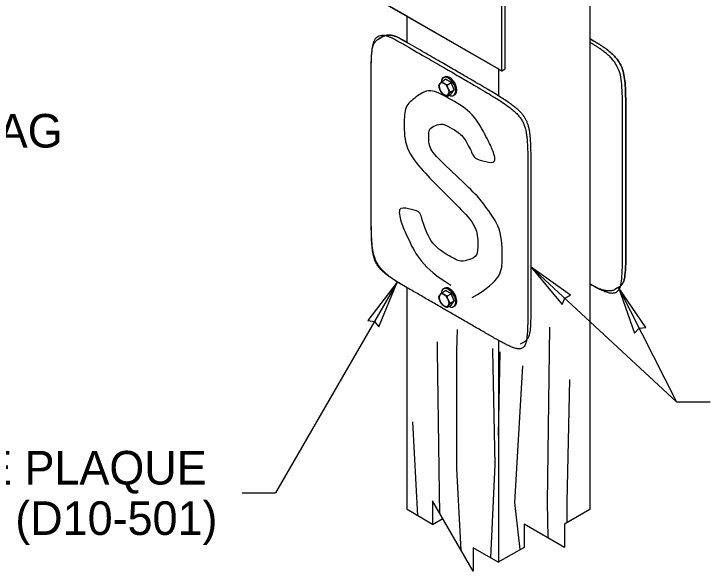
# Model space of a CAD drawing. Extents: x 99862 to 103151, y 100000 to 102076.
# Drawn here: x 101949.6 to 102281.3, y 100780.9 to 101046.3 of the extents above; entities that cross this region are included whole.
import ezdxf

# ---------------------------------------------------------------- set-up
doc = ezdxf.new("R2010")
doc.units = 0
for name, color, linetype in [('Level 11', 7, 'Continuous'), ('Level 15', 7, 'Continuous'), ('Level 2', 7, 'Continuous'), ('Level 20', 7, 'Continuous'), ('Level 9', 7, 'Continuous')]:
    doc.layers.add(name, color=color, linetype=linetype)

msp = doc.modelspace()

# ---------------------------------------------------------------- linework, layer by layer
at = {"layer": 'Level 11'}
for points in [[(102160.68, 100886.06), (102160.91, 100895.92)], [(102203.82, 100813.64), (102204.88, 100897.15)], [(102151.36, 100886.06), (102151.41, 100890.11)], [(102152.58, 100808.28), (102152.46, 100818.42), (102151.36, 100886.06)], [(102162.68, 100790.78), (102160.68, 100829.72), (102160.68, 100886.06)], [(102176.78, 100787.2), (102178.97, 100831.6), (102177.8, 100886.06)], [(102177.8, 100886.06), (102177.78, 100886.86)], [(102180.47, 100845.54), (102181.23, 100885.3)], [(102188.31, 100813.64), (102192.1, 100878.71)], [(102213.14, 100813.64), (102214.51, 100872.09)], [(102142.07, 100807.24), (102139.68, 100852)], [(102190.86, 100791.13), (102188.31, 100813.64)], [(102204.09, 100796.69), (102203.82, 100813.64)], [(102213.14, 100803.99), (102213.14, 100813.64)]]:
    msp.add_lwpolyline(points, dxfattribs=at)
at = {"layer": 'Level 15'}
for p, q in [((102136.96, 101032.65), (102136.96, 101045.22)), ((102125.04, 101035.32), (102123.49, 101034.42)), ((102196.07, 100925.65), (102265.31, 100861.47)), ((102132.29, 100918.58), (102074.3, 100818.14)), ((102237.54, 100915.92), (102235.98, 100915.02)), ((102237.64, 100915.97), (102265.31, 100861.47)), ((102192.43, 100889.87), (102190.87, 100888.97)), ((102265.31, 100861.47), (102281.31, 100861.47)), ((102058.3, 100818.14), (102074.3, 100818.14)), ((102149.1, 100803.18), (102153.92, 100805.96))]:
    msp.add_line(p, q, dxfattribs=at)
for points in [[(102196.07, 100925.65), (102210.78, 100907.94), (102212.04, 100910.85), (102214.84, 100912.32)], [(102132.29, 100918.58), (102118.29, 100900.31), (102121.4, 100899.73), (102123.46, 100897.32)], [(102237.64, 100915.97), (102245.31, 100894.27), (102247.49, 100896.56), (102250.63, 100896.97)]]:
    msp.add_lwpolyline(points, close=True, dxfattribs=at)
for points in [[(102136.96, 100810.19), (102136.96, 100915.89)], [(102180.41, 100785.1), (102168.37, 100792.05), (102168.37, 100780.92), (102149.1, 100814.3), (102149.1, 100803.18), (102136.96, 100810.19)], [(102224.07, 100810.31), (102211.93, 100803.3), (102211.93, 100792.17), (102192.66, 100803.3), (102192.66, 100792.17), (102180.41, 100785.1)]]:
    msp.add_lwpolyline(points, dxfattribs=at)
for points, degree in [([(102132.29, 101033.55), (102119.84, 101040.73), (102119.84, 101026.36), (102119.84, 100983.25), (102119.84, 100940.14), (102119.84, 100925.77), (102132.29, 100918.58), (102157.18, 100904.21), (102182.07, 100889.84), (102194.51, 100882.66), (102194.51, 100897.03), (102194.51, 100940.14), (102194.51, 100983.25), (102194.51, 100997.62), (102182.07, 101004.81), (102157.18, 101019.18), (102132.29, 101033.55)], 4), ([(102133.84, 101034.44), (102128.69, 101037.42), (102125.04, 101035.32)], 2), ([(102192.43, 100889.87), (102196.07, 100891.97), (102196.07, 100897.93), (102196.07, 100941.04), (102196.07, 100984.15), (102196.07, 100998.52), (102183.63, 101005.7), (102158.73, 101020.07), (102133.84, 101034.44)], 4), ([(102237.54, 100915.92), (102241.18, 100918.02), (102241.18, 100923.97), (102241.18, 100967.08), (102241.18, 101010.19), (102241.18, 101024.56), (102228.74, 101031.75), (102226.41, 101033.1), (102224.07, 101034.44)], 4), ([(102224.07, 100917.69), (102225.63, 100916.79), (102227.18, 100915.89), (102239.63, 100908.7), (102239.63, 100923.07), (102239.63, 100966.19), (102239.63, 101009.3), (102239.63, 101023.67), (102227.18, 101030.85), (102225.63, 101031.75), (102224.07, 101032.65)], 4)]:
    msp.add_open_spline(points, degree=degree, dxfattribs=at)
at = {"layer": 'Level 2'}
for p, q in [((102180.51, 101020.07), (102180.51, 101007.5)), ((102182.07, 101019.18), (102183.63, 101020.07))]:
    msp.add_line(p, q, dxfattribs=at)
for points in [[(102136.96, 101435.02), (102180.51, 101460.17), (102224.07, 101435.02), (102224.07, 101034.44)], [(102180.51, 101460.17), (102224.07, 101435.02), (102224.07, 100810.31)], [(102119.84, 101055.1), (102182.07, 101019.18), (102182.07, 101407.17), (102119.84, 101443.1)], [(102119.84, 101055.1), (102136.96, 101045.22), (102180.51, 101020.07), (102182.07, 101019.18), (102182.07, 101407.17), (102119.84, 101443.1)], [(102136.96, 101032.65), (102136.96, 101045.22), (102119.84, 101055.1)], [(102123.49, 101034.42), (102123.49, 101034.42), (102125.04, 101035.32)], [(102154.22, 101015.93), (102154.73, 101016.22)], [(102156.88, 101007.58), (102156.14, 101007.16)], [(102159.62, 101007.76), (102159.11, 101007.46)], [(102136.96, 100810.19), (102136.96, 100915.89)], [(102154.22, 100915.33), (102154.73, 100915.63)], [(102224.07, 100917.69), (102224.07, 100810.31)], [(102237.54, 100915.92), (102235.98, 100915.02), (102235.98, 100915.02)], [(102156.88, 100906.99), (102156.14, 100906.57)], [(102159.62, 100907.16), (102159.11, 100906.86)], [(102180.51, 100890.74), (102180.51, 100785.04)]]:
    msp.add_lwpolyline(points, dxfattribs=at)
for centre, major_axis, start_param, end_param in [((102156.66, 101011.69), (2.44, -4.23), 3.141593, 3.891684), ((102157.18, 101011.99), (2.44, -4.23), 6.283184, 9.424781), ((102154.59, 101010.51), (1.65, -2.86), 3.3825, 3.424282), ((102154.59, 101010.51), (1.65, -2.86), 4.423348, 4.477829), ((102154.59, 101010.51), (1.65, -2.86), 5.47306, 5.52251), ((102156.66, 101011.69), (2.44, -4.23), 5.560453, 6.283185), ((102156.66, 100911.1), (2.44, -4.23), 3.141593, 3.891684), ((102157.18, 100911.4), (2.44, -4.23), 6.283184, 9.424781), ((102154.59, 100909.92), (1.65, -2.86), 3.3825, 3.424282), ((102154.59, 100909.92), (1.65, -2.86), 4.423348, 4.477829), ((102154.59, 100909.92), (1.65, -2.86), 5.47306, 5.52251), ((102156.66, 100911.1), (2.44, -4.23), 5.560453, 6.283185)]:
    msp.add_ellipse(centre, major_axis=major_axis, ratio=0.57735, start_param=start_param, end_param=end_param, dxfattribs=at)
for points, degree in [([(102183.63, 101020.07), (102183.63, 101214.07), (102183.63, 101408.07), (102152.51, 101426.04), (102121.4, 101444), (102071.62, 101472.74), (102021.84, 101501.48), (102016.68, 101504.46), (102013.04, 101502.35)], 4), ([(102136.96, 100915.89), (102134.62, 100917.24), (102132.29, 100918.58), (102119.84, 100925.77), (102119.84, 100940.14), (102119.84, 100983.25), (102119.84, 101026.36), (102119.84, 101032.31), (102123.49, 101034.42)], 4), ([(102125.04, 101035.32), (102128.69, 101037.42), (102133.84, 101034.44)], 2), ([(102133.84, 101034.44), (102135.4, 101033.55), (102136.96, 101032.65)], 2), ([(102224.07, 101034.44), (102226.41, 101033.1), (102228.74, 101031.75), (102241.18, 101024.56), (102241.18, 101010.19), (102241.18, 100967.08), (102241.18, 100923.97), (102241.18, 100918.02), (102237.54, 100915.92)], 4), ([(102152.1, 101012.19), (102152.19, 101012.42), (102152.33, 101012.68), (102152.54, 101012.99)], 2), ([(102152.54, 101010.41), (102152.32, 101010.98), (102152.19, 101011.57), (102152.1, 101012.19)], 2), ([(102152.59, 101013.06), (102152.76, 101013.3), (102152.97, 101013.55), (102153.21, 101013.83)], 2), ([(102168.03, 100911.24), (102182.26, 100919.19), (102182.26, 100929.7), (102182.26, 100944.11), (102173.16, 100956.1), (102170.36, 100959.88), (102156.25, 100973.15), (102147.26, 100981.57), (102147.26, 100987.63), (102147.26, 100991.8), (102150.47, 100993.12), (102153.68, 100994.43), (102158.23, 100991.8), (102163.25, 100988.91), (102166.63, 100982.64), (102167.68, 100980.69), (102168.85, 100977.19), (102174.39, 100976.01), (102179.93, 100974.83), (102177.48, 100982.31), (102175.26, 100986.55), (102168.61, 100999.28), (102158.23, 101005.28), (102147.5, 101011.47), (102140.96, 101006.49), (102135.59, 101002.45), (102135.59, 100994.36), (102135.59, 100982.24), (102144.7, 100971.19), (102153.1, 100962.7), (102161.61, 100954.28), (102170.6, 100944.92), (102170.6, 100936.43), (102170.6, 100930.78), (102166.63, 100929.29), (102162.66, 100927.81), (102157.76, 100930.64), (102148.31, 100936.1), (102144.35, 100947.55), (102143.76, 100949.37), (102143.18, 100952.26), (102137.64, 100953.44), (102132.09, 100954.62), (102134.43, 100945.73), (102136.88, 100940.54), (102144.35, 100924.92), (102157.76, 100917.17)], 3), ([(102153.45, 101008.71), (102153.12, 101009.18), (102152.82, 101009.69), (102152.6, 101010.25)], 2), ([(102154.53, 101007.85), (102154.1, 101008.1), (102153.75, 101008.4), (102153.45, 101008.71)], 2), ([(102156.14, 101007.16), (102155.6, 101007.33), (102155.09, 101007.53), (102154.64, 101007.78)], 2), ([(102235.98, 100915.02), (102232.34, 100912.91), (102227.18, 100915.89), (102225.63, 100916.79), (102224.07, 100917.69)], 4), ([(102152.1, 100911.59), (102152.19, 100911.82), (102152.33, 100912.08), (102152.54, 100912.4)], 2), ([(102152.54, 100909.82), (102152.32, 100910.39), (102152.19, 100910.98), (102152.1, 100911.59)], 2), ([(102152.59, 100912.47), (102152.76, 100912.7), (102152.97, 100912.96), (102153.21, 100913.23)], 2), ([(102153.45, 100908.12), (102153.12, 100908.59), (102152.82, 100909.1), (102152.6, 100909.65)], 2), ([(102154.53, 100907.26), (102154.1, 100907.51), (102153.75, 100907.81), (102153.45, 100908.12)], 2), ([(102156.14, 100906.57), (102155.6, 100906.74), (102155.09, 100906.94), (102154.64, 100907.19)], 2)]:
    msp.add_open_spline(points, degree=degree, dxfattribs=at)
at = {"layer": 'Level 9'}
for p, q in [((102153.45, 101014.1), (102155.31, 101015.18)), ((102154.22, 101015.93), (102154.73, 101016.22)), ((102158.01, 101013.62), (102155.31, 101015.18)), ((102152.59, 101013.06), (102152.54, 101012.99)), ((102156.14, 101012.55), (102158.01, 101013.62)), ((102159.36, 101010.15), (102158.01, 101013.62)), ((102152.54, 101010.41), (102152.6, 101010.25)), ((102154.53, 101007.85), (102154.64, 101007.78)), ((102156.14, 101007.16), (102158.01, 101008.24)), ((102156.59, 101007.97), (102156.62, 101008.02)), ((102157.49, 101009.07), (102159.36, 101010.15)), ((102158.01, 101008.24), (102159.36, 101010.15)), ((102159.62, 101007.76), (102159.11, 101007.46)), ((102154.22, 100915.33), (102154.73, 100915.63)), ((102152.59, 100912.47), (102152.54, 100912.4)), ((102153.45, 100913.51), (102155.31, 100914.59)), ((102158.01, 100913.03), (102155.31, 100914.59)), ((102156.14, 100911.95), (102158.01, 100913.03)), ((102159.36, 100909.56), (102158.01, 100913.03)), ((102152.54, 100909.82), (102152.6, 100909.65)), ((102157.49, 100908.48), (102159.36, 100909.56)), ((102158.01, 100907.64), (102159.36, 100909.56)), ((102154.53, 100907.26), (102154.64, 100907.19)), ((102156.14, 100906.57), (102158.01, 100907.64)), ((102156.59, 100907.38), (102156.62, 100907.43)), ((102159.62, 100907.16), (102159.11, 100906.86))]:
    msp.add_line(p, q, dxfattribs=at)
for centre, major_axis, start_param, end_param in [((102156.66, 101011.69), (2.44, -4.23), 5.560453, 10.174869), ((102157.18, 101011.99), (2.44, -4.23), 6.283184, 9.424781), ((102154.59, 101010.51), (1.65, -2.86), 2.356194, 8.638997), ((102156.66, 100911.1), (2.44, -4.23), 5.560453, 10.174869), ((102157.18, 100911.4), (2.44, -4.23), 6.283184, 9.424781), ((102154.59, 100909.92), (1.65, -2.86), 2.356194, 8.638997)]:
    msp.add_ellipse(centre, major_axis=major_axis, ratio=0.57735, start_param=start_param, end_param=end_param, dxfattribs=at)
for points, degree in [([(102152.54, 101012.99), (102152.33, 101012.68), (102152.19, 101012.42), (102152.1, 101012.19)], 2), ([(102152.1, 101012.19), (102152.19, 101011.57), (102152.32, 101010.98), (102152.54, 101010.41)], 2), ([(102153.45, 101014.1), (102153.11, 101013.73), (102152.82, 101013.38), (102152.59, 101013.06)], 2), ([(102153.45, 101014.1), (102153.76, 101013.78), (102154.13, 101013.47), (102154.59, 101013.2)], 2), ([(102154.59, 101013.2), (102155.04, 101012.94), (102155.58, 101012.73), (102156.14, 101012.55)], 2), ([(102157.49, 101009.07), (102157.14, 101009.57), (102156.84, 101010.1), (102156.38, 101011.28), (102156.24, 101011.91), (102156.14, 101012.55)], 3), ([(102152.6, 101010.25), (102152.82, 101009.69), (102153.12, 101009.18), (102153.45, 101008.71)], 2), ([(102153.45, 101008.71), (102153.75, 101008.4), (102154.1, 101008.1), (102154.53, 101007.85)], 2), ([(102154.64, 101007.78), (102155.09, 101007.53), (102155.6, 101007.33), (102156.14, 101007.16)], 2), ([(102156.14, 101007.16), (102156.23, 101007.39), (102156.37, 101007.66), (102156.59, 101007.97)], 2), ([(102156.62, 101008.02), (102156.85, 101008.34), (102157.15, 101008.7), (102157.49, 101009.07)], 2), ([(102152.54, 100912.4), (102152.33, 100912.08), (102152.19, 100911.82), (102152.1, 100911.59)], 2), ([(102152.1, 100911.59), (102152.19, 100910.98), (102152.32, 100910.39), (102152.54, 100909.82)], 2), ([(102153.45, 100913.51), (102153.11, 100913.14), (102152.82, 100912.78), (102152.59, 100912.47)], 2), ([(102153.45, 100913.51), (102153.76, 100913.18), (102154.13, 100912.87), (102154.59, 100912.61)], 2), ([(102154.59, 100912.61), (102155.04, 100912.35), (102155.58, 100912.13), (102156.14, 100911.95)], 2), ([(102157.49, 100908.48), (102157.14, 100908.98), (102156.84, 100909.5), (102156.38, 100910.68), (102156.24, 100911.31), (102156.14, 100911.95)], 3), ([(102152.6, 100909.65), (102152.82, 100909.1), (102153.12, 100908.59), (102153.45, 100908.12)], 2), ([(102153.45, 100908.12), (102153.75, 100907.81), (102154.1, 100907.51), (102154.53, 100907.26)], 2), ([(102156.62, 100907.43), (102156.85, 100907.75), (102157.15, 100908.1), (102157.49, 100908.48)], 2), ([(102154.64, 100907.19), (102155.09, 100906.94), (102155.6, 100906.74), (102156.14, 100906.57)], 2), ([(102156.14, 100906.57), (102156.23, 100906.8), (102156.37, 100907.06), (102156.59, 100907.38)], 2)]:
    msp.add_open_spline(points, degree=degree, dxfattribs=at)

# ---------------------------------------------------------------- texts
at = {"layer": 'Level 20'}
for s, p in [('1/4" DIAM. × 1 1/2" LAG', (101741.77, 100982.64)), ('SPUR ROUTE PLAQUE', (101808.43, 100822.14)), ('(D10-501)', (101950.26, 100798.14))]:
    msp.add_text(s, height=16, dxfattribs=at).set_placement(p)

doc.saveas('drawing.dxf')
